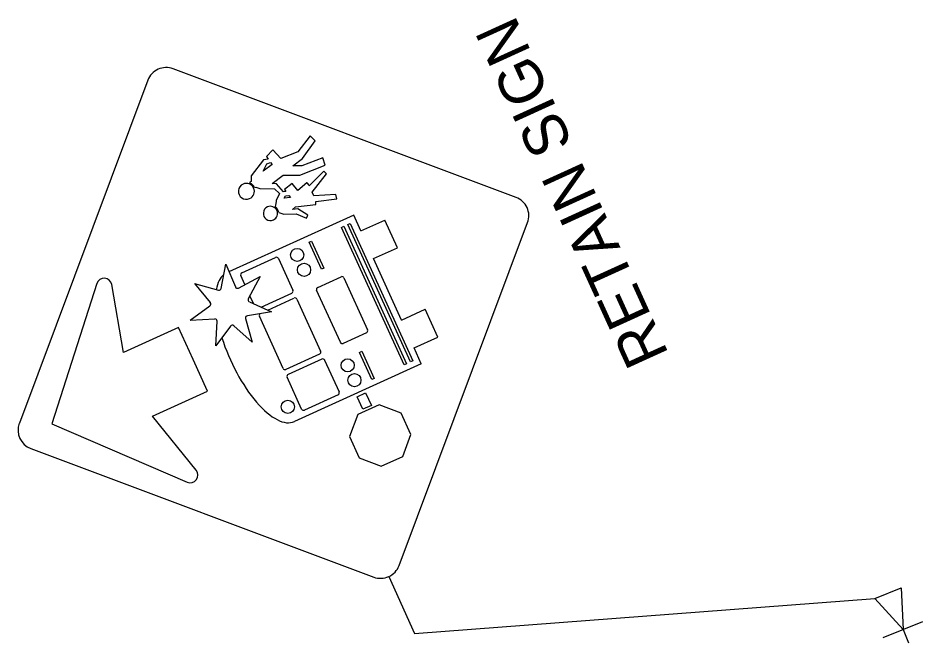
# Model space of a CAD drawing. Extents: x 2096093 to 2098911, y 683546 to 689764.
# Drawn here: x 2096490.3 to 2096634.9, y 684459.5 to 684559.4 of the extents above; entities that cross this region are included whole.
import ezdxf

# ---------------------------------------------------------------- set-up
doc = ezdxf.new("R2010")
doc.units = 0
doc.layers.add('Default', color=7, linetype='Continuous')
doc.layers.add('Prop DSN Text', color=7, linetype='Continuous')

msp = doc.modelspace()

# ---------------------------------------------------------------- linework, layer by layer
at = {"layer": 'Default'}
for p, q in [((2096627.22, 684466.65), (2096631.47, 684468.33)), ((2096631.47, 684468.33), (2096631.78, 684461.68)), ((2096631.78, 684461.68), (2096627.22, 684466.65)), ((2096628.59, 684460.42), (2096634.92, 684462.93)), ((2096631.78, 684461.68), (2096632.63, 684459.53))]:
    msp.add_line(p, q, dxfattribs=at)
at = {"layer": 'Prop DSN Text'}
for p, q in [((2096532.86, 684530.6), (2096532.86, 684530.6)), ((2096533.06, 684530.97), (2096533.06, 684530.97)), ((2096533.61, 684531.01), (2096533.61, 684531.01)), ((2096533.85, 684530.71), (2096533.85, 684530.71)), ((2096531.47, 684529.48), (2096531.47, 684529.48)), ((2096531.55, 684530.05), (2096531.55, 684530.05)), ((2096543.96, 684527.91), (2096524.02, 684518.84)), ((2096532.8, 684528.05), (2096532.8, 684528.05)), ((2096534.76, 684528.12), (2096534.76, 684528.12)), ((2096536.4, 684527.42), (2096536.4, 684527.42)), ((2096536.62, 684527.88), (2096536.62, 684527.88)), ((2096545.11, 684525.37), (2096543.96, 684527.91)), ((2096545.11, 684525.37), (2096548.92, 684527.11)), ((2096550.94, 684522.67), (2096548.92, 684527.11)), ((2096547.13, 684520.94), (2096550.94, 684522.67)), ((2096526.11, 684518.69), (2096531.47, 684521.13)), ((2096531.93, 684520.96), (2096534.24, 684515.89)), ((2096551.6, 684511.11), (2096547.13, 684520.94)), ((2096522.79, 684516.17), (2096523.54, 684520.04)), ((2096523.54, 684520.04), (2096525.06, 684516.41)), ((2096503.04, 684517.3), (2096503.04, 684517.3)), ((2096525.54, 684516.23), (2096529.03, 684518.06)), ((2096526.59, 684516.78), (2096525.93, 684518.23)), ((2096529.03, 684518.06), (2096527.12, 684514.54)), ((2096518.5, 684516.95), (2096521.05, 684513.91)), ((2096518.5, 684516.95), (2096522.36, 684515.9)), ((2096527.97, 684513.76), (2096527.39, 684515.02)), ((2096529.17, 684513.2), (2096534.06, 684515.42)), ((2096530.23, 684512.72), (2096534.42, 684514.63)), ((2096534.89, 684514.46), (2096538.67, 684506.13)), ((2096517.84, 684511.12), (2096520.98, 684513.4)), ((2096527.29, 684514.06), (2096530.83, 684512.45)), ((2096530.83, 684512.45), (2096526.98, 684511.82)), ((2096532.68, 684503.4), (2096528.89, 684511.73)), ((2096551.6, 684511.11), (2096555.41, 684512.84)), ((2096557.43, 684508.4), (2096555.41, 684512.84)), ((2096517.84, 684511.12), (2096521.78, 684511.31)), ((2096521.94, 684507.01), (2096522.14, 684510.94)), ((2096524.3, 684510.17), (2096521.94, 684507.01)), ((2096527.76, 684507.61), (2096524.81, 684510.22)), ((2096526.7, 684511.38), (2096527.76, 684507.61)), ((2096553.62, 684506.67), (2096557.43, 684508.4)), ((2096554.77, 684504.13), (2096553.62, 684506.67)), ((2096538.5, 684505.67), (2096533.14, 684503.23)), ((2096538.86, 684504.88), (2096533.5, 684502.44)), ((2096539.32, 684504.71), (2096541.63, 684499.63)), ((2096554.77, 684504.13), (2096534.48, 684494.9)), ((2096535.63, 684496.9), (2096533.33, 684501.98)), ((2096541.46, 684499.17), (2096536.09, 684496.73)), ((2096548.03, 684497.57), (2096544.62, 684496.02)), ((2096551.55, 684496.26), (2096548.03, 684497.57)), ((2096544.62, 684496.02), (2096543.3, 684492.5)), ((2096553.1, 684492.84), (2096551.55, 684496.26)), ((2096551.79, 684489.32), (2096553.1, 684492.84)), ((2096543.3, 684492.5), (2096544.85, 684489.09)), ((2096544.85, 684489.09), (2096548.37, 684487.77)), ((2096548.37, 684487.77), (2096551.79, 684489.32))]:
    msp.add_line(p, q, dxfattribs=at)
for points in [[(2096569.91, 684530.73), (2096515.11, 684551.26)], [(2096511.07, 684549.43), (2096490.54, 684494.62)], [(2096531.99, 684528.31), (2096532.8, 684528.05), (2096534.76, 684528.12), (2096536.4, 684527.42), (2096536.62, 684527.88), (2096535.02, 684528.9), (2096534.2, 684528.77), (2096534.69, 684529.23), (2096537.91, 684529.6), (2096537.89, 684530.07), (2096541.29, 684530.49), (2096541.11, 684531.19), (2096537.58, 684530.96), (2096537.32, 684531.57), (2096539.63, 684534.51), (2096539.21, 684534.93), (2096536.86, 684532.57), (2096536.8, 684532.68), (2096536.75, 684532.79), (2096536.66, 684532.92), (2096536.57, 684533), (2096536.48, 684533.05), (2096535.05, 684531.84), (2096534.13, 684532.94), (2096532.88, 684532), (2096533.13, 684531.64), (2096532.77, 684531.63), (2096531.65, 684532.87), (2096530.92, 684532.96), (2096532.69, 684534.27), (2096535.34, 684534.27), (2096539.39, 684535.89), (2096539.05, 684537.02), (2096535.67, 684535.76), (2096534.24, 684535.79), (2096535.78, 684536.95), (2096537.8, 684539.76), (2096536.99, 684540.58), (2096535.05, 684538), (2096532.34, 684536.92), (2096531.02, 684538.32), (2096530.03, 684537.28), (2096530.3, 684536.84), (2096529.53, 684536.7), (2096527.6, 684534.15), (2096527.58, 684533.28), (2096527.36, 684533.14), (2096527.38, 684533.02)], [(2096530.67, 684536.32), (2096530.93, 684535.98), (2096529.52, 684534.9), (2096530.1, 684536.11), (2096530.67, 684536.32)], [(2096528.12, 684532.31), (2096528.31, 684532.38), (2096528.96, 684532.13), (2096529.02, 684532.14), (2096531.29, 684532.08), (2096532.12, 684531.34), (2096531.6, 684530.23), (2096531.55, 684530.05), (2096531.47, 684529.48)], [(2096533.61, 684531.01), (2096533.85, 684530.71), (2096532.86, 684530.6), (2096533.06, 684530.97), (2096533.61, 684531.01)], [(2096531.47, 684529.48), (2096531.42, 684529.26)], [(2096551.21, 684471.89), (2096571.74, 684526.69)], [(2096538.21, 684516.35), (2096541.94, 684518.05)], [(2096542.4, 684517.88), (2096546.19, 684509.55)], [(2096502.93, 684516.95), (2096495.71, 684494.53), (2096517.36, 684485.23)], [(2096518.3, 684504.84), (2096515.99, 684509.92), (2096507.2, 684505.92), (2096505.29, 684516.79)], [(2096541.83, 684507.57), (2096538.04, 684515.89)], [(2096546.01, 684509.09), (2096542.29, 684507.39)], [(2096518.79, 684487.11), (2096511.8, 684495.76), (2096520.61, 684499.77), (2096518.3, 684504.84)], [(2096492.37, 684490.59), (2096547.17, 684470.05)], [(2096549.57, 684470.14), (2096553.7, 684461.05), (2096627.22, 684466.65)]]:
    msp.add_lwpolyline(points, dxfattribs=at)
for points in [[(2096552.02, 684503.98), (2096542.03, 684525.93), (2096542.41, 684526.1), (2096552.39, 684504.15)], [(2096553.03, 684504.44), (2096543.05, 684526.39), (2096543.42, 684526.56), (2096553.41, 684504.61)], [(2096538.83, 684519.25), (2096536.86, 684523.58), (2096537.24, 684523.75), (2096539.21, 684519.42)], [(2096546.84, 684501.63), (2096544.88, 684505.96), (2096545.25, 684506.13), (2096547.22, 684501.8)], [(2096545.87, 684499.49), (2096546.79, 684497.47), (2096545.44, 684496.86), (2096544.53, 684498.88)]]:
    msp.add_lwpolyline(points, close=True, dxfattribs=at)
for centre in [(2096534.94, 684521.53), (2096536.03, 684519.15), (2096543, 684503.89), (2096544.08, 684501.51), (2096533.44, 684497.25)]:
    msp.add_circle(centre, 1.05, dxfattribs=at)
for centre, radius, start, end in [((2096514.01, 684548.33), 3.14, 69.4559, 159.458), ((2096526.81, 684531.69), 1.28, 114.458, 294.458), ((2096526.81, 684531.69), 1.28, 294.458, 114.458), ((2096526.82, 684531.69), 1.44, 25.2657, 67.1381), ((2096568.81, 684527.79), 3.14, 339.4559, 69.458), ((2096530.66, 684528.16), 1.14, 114.458, 294.458), ((2096530.66, 684528.16), 1.14, 294.458, 114.458), ((2096530.66, 684528.16), 1.33, 6.57, 55.3516), ((2096531.61, 684520.81), 0.348, 24.458, 114.458), ((2096504.09, 684516.58), 1.22, 9.9853, 162.16), ((2096526.25, 684518.38), 0.348, 114.458, 204.458), ((2096542.08, 684517.73), 0.348, 24.458, 114.458), ((2096522.45, 684516.24), 0.348, 254.7728, 349.1199), ((2096525.38, 684516.54), 0.348, 202.6931, 297.6908), ((2096533.92, 684515.74), 0.348, 294.458, 24.458), ((2096538.36, 684516.04), 0.348, 114.458, 204.458), ((2096527.43, 684514.37), 0.348, 151.6716, 245.6888), ((2096534.57, 684514.31), 0.348, 24.458, 114.458), ((2096520.78, 684513.68), 0.348, 305.9926, 39.9359), ((2096527.03, 684511.48), 0.348, 99.3189, 195.734), ((2096529.21, 684511.88), 0.348, 138.9148, 204.458), ((2096521.79, 684510.96), 0.348, 357.0816, 92.756), ((2096524.57, 684509.96), 0.348, 48.5085, 143.3177), ((2096545.87, 684509.41), 0.348, 294.458, 24.458), ((2096542.14, 684507.71), 0.348, 204.458, 294.458), ((2096538.36, 684505.99), 0.348, 294.458, 24.458), ((2096539.01, 684504.56), 0.348, 24.458, 114.458), ((2096532.99, 684503.55), 0.348, 204.458, 294.458), ((2096533.64, 684502.12), 0.348, 114.458, 204.458), ((2096541.31, 684499.49), 0.348, 294.458, 24.458), ((2096535.95, 684497.05), 0.348, 204.458, 294.458), ((2096493.47, 684493.52), 3.14, 159.458, 249.458), ((2096517.84, 684486.35), 1.22, 246.7557, 38.9307), ((2096548.27, 684472.99), 3.14, 249.458, 339.458)]:
    msp.add_arc(centre, radius, start, end, dxfattribs=at)
for start_param, end_param in [(0.098799, 0.527026), (1.265977, 3.141593)]:
    msp.add_ellipse((2096529.07, 684506.79), major_axis=(-5.41, 11.89), ratio=0.399852, start_param=start_param, end_param=end_param, dxfattribs=at)

# ---------------------------------------------------------------- texts
at = {"layer": 'Default'}
msp.add_text('RETAIN SIGN', height=7, rotation=114.4888, dxfattribs=at).set_placement((2096594.38, 684505.64))

doc.saveas('drawing.dxf')
